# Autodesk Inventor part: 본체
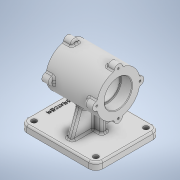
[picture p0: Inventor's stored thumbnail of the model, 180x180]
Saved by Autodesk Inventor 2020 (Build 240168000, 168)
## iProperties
Created: 2022-11
Part Number: 본체
Material: 일반
Document SubType Name: Modeling
Designer: owner
Density: 1 g/cm^3
Appearance: 기본값
Mass: 450.167 g
Surface Area: 796.807 cm^2
Volume: 450.167 cm^3
Author: owner
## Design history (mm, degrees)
sketch "스케치1"
  geometry: L1 (-65, -55)-(65, -55); L2 (65, -55)-(65, 55); L3 (65, 55)-(-65, 55); L4 (-65, 55)-(-65, -55); L5 (-65, -55)-(65, 55); L6 (65, -55)-(-65, 55); 1 further point
  constraints: 12 end point, 2 midpoint, 2 parallel, 1 horizontal, 1 perpendicular
  dimensions: "d0" = 130 distance of L3.end L2.end; "d1" = 110 distance of L2.end L1.end
extrude "돌출1" new body sketch "스케치1" distance "d2" = 12; taper "d3" = 0 deg
node "작업 평면1"
sketch "스케치3"
  geometry: L1 (110, 0)-(0, 0) reference; C1 r 37 at (55, 82); 2 further points
  constraints: 1 centre point, 1 midpoint, 1 vertical alignment
  dimensions: "d13" = 82 distance from line of L1 C1.centre; "d14" = 74 diameter of C1
extrude "돌출2" join sketch "스케치3" stored distance "d15" = 87; taper "d16" = 0 deg
sketch "스케치4"
  geometry: C1 r 37 at (0, 0) reference; A1 r 37 centre (0, 0) between (0, 37) and (-6.969, 36.338) reference; A2 r 7 centre (0, 37) between (6.969, 36.338) and (-6.969, 36.338); A3 r 7 centre (-37, 0) between (-36.338, 6.969) and (-36.338, -6.969); A4 r 7 centre (0, -37) between (-6.969, -36.338) and (6.969, -36.338); A5 r 7 centre (37, 0) between (36.338, -6.969) and (36.338, 6.969); 9 further points
  constraints: 11 point on circle, 4 centre point, 1 coincident, 1 vertical alignment, 17 other
  dimensions: "d17" = 14 diameter of A2; "d20" = 360 deg dimension on C1.centre A2.centre (derived)
extrude "돌출3" join sketch "스케치4" distance "d22" = 14; taper "d23" = 0 deg
sketch "스케치5"
  geometry: L1 (110, 0)-(0, 0) reference; L2 (0, 0)-(0, 12) reference; L3 (110, 12)-(0, 12) reference; L4 (110, 0)-(110, 12) reference; L5 (80.336, 55.036)-(96, 12); L6 (0, 12)-(110, 12) reference; L7 (29.664, 55.036)-(14, 12); A1 r 37 centre (55, 82) between (61.969, 45.662) and (91.338, 75.031) reference; A2 r 7 centre (55, 45) between (48.031, 45.662) and (61.969, 45.662) reference; A3 r 37 centre (55, 82) between (18.662, 75.031) and (48.031, 45.662) reference; A4 r 7 centre (18, 82) between (18.662, 88.969) and (18.662, 75.031) reference; A5 r 37 centre (55, 82) between (48.031, 118.338) and (18.662, 88.969) reference; A6 r 7 centre (55, 119) between (61.969, 118.338) and (48.031, 118.338) reference; A7 r 37 centre (55, 82) between (91.338, 88.969) and (61.969, 118.338) reference; A8 r 7 centre (92, 82) between (91.338, 75.031) and (91.338, 88.969) reference; A9 r 37 centre (55, 82) between (61.969, 45.662) and (91.338, 75.031) reference; A10 r 37 centre (55, 82) between (18.662, 75.031) and (48.031, 45.662) reference; A11 r 7 centre (55, 45) between (48.031, 45.662) and (61.969, 45.662) reference; A12 r 37 centre (55, 82) between (48.031, 45.662) and (61.969, 45.662) reference; 4 further points
  constraints: 4 end point, 2 point on circle, 2 point on line, 1 equal length
  dimensions: "d24" = 110 deg angle of L3 L5; "d25" = 110 deg angle of L3 L7; "d26" = 14 distance of L7.end L2.end
extrude "돌출4" join sketch "스케치5" stored distance "d27" = 10; taper "d28" = 0 deg
sketch "스케치6"
  geometry: L1 (-65, 0)-(65, 0) reference; L2 (65, 0)-(65, 12) reference; L3 (-65, 12)-(65, 12) reference; L4 (-65, 0)-(-65, 12) reference; L5 (0, 12)-(0, 55.036) reference; L6 (10, 55.036)-(10, 55.036) reference; L7 (10, 55.036)-(0, 55.036) reference; L8 (0, 55.036)-(0, 55.036) reference; L9 (0, 55.036)-(10, 55.036) reference; L10 (48.5, 45.662)-(34.5, 45.662) reference; L11 (34.5, 45.662)-(34.5, 45.662) reference; L12 (34.5, 45.662)-(48.5, 45.662) reference; L13 (48.5, 75.031)-(48.5, 45.662) reference; L14 (48.5, 75.031)-(34.5, 75.031) reference; L15 (34.5, 75.031)-(34.5, 88.969) reference; L16 (34.5, 88.969)-(48.5, 88.969) reference; L17 (48.5, 118.338)-(48.5, 88.969) reference; L18 (48.5, 118.338)-(34.5, 118.338) reference; L19 (34.5, 118.338)-(34.5, 118.338) reference; L20 (34.5, 118.338)-(48.5, 118.338) reference; L21 (48.5, 88.969)-(48.5, 118.338) reference; L22 (48.5, 88.969)-(34.5, 88.969) reference; L23 (34.5, 88.969)-(34.5, 75.031) reference; L24 (34.5, 75.031)-(48.5, 75.031) reference; L25 (48.5, 45.662)-(48.5, 75.031) reference; L26 (-38.5, 45.662)-(-24.5, 45.662) reference; L27 (-24.5, 45.662)-(-24.5, 45.662) reference; L28 (-24.5, 45.662)-(-38.5, 45.662) reference; L29 (-38.5, 75.031)-(-38.5, 45.662) reference; L30 (-38.5, 75.031)-(-24.5, 75.031) reference; L31 (-24.5, 75.031)-(-24.5, 88.969) reference; L32 (-24.5, 88.969)-(-38.5, 88.969) reference; L33 (-38.5, 118.338)-(-38.5, 88.969) reference; L34 (-38.5, 118.338)-(-24.5, 118.338) reference; L35 (-24.5, 118.338)-(-24.5, 118.338) reference; L36 (-24.5, 118.338)-(-38.5, 118.338) reference; L37 (-38.5, 88.969)-(-38.5, 118.338) reference; L38 (-38.5, 88.969)-(-24.5, 88.969) reference; L39 (-24.5, 88.969)-(-24.5, 75.031) reference; L40 (-24.5, 75.031)-(-38.5, 75.031) reference; L41 (-38.5, 45.662)-(-38.5, 75.031) reference; L42 (34.5, 45)-(-24.5, 45) reference; L43 (65, 12)-(-65, 12) reference; L44 (-15, 45)-(-15, 12); L45 (5, -25.2)-(5, 151.2) reference; 1 further point
  constraints: 2 end point, 2 point on line, 1 perpendicular
  dimensions: "d31" = 20 distance from line of L45 L44.end
feature "리브1" sketch "스케치6" dims "d32" = 1, "d33" = 10, "d34" = 0, "d35" = 0, "d36" = 1, "d37" = 1
sketch "스케치7"
  geometry: A1 r 7 centre (55, 45) between (48.031, 45.662) and (61.969, 45.662) reference; A2 r 37 centre (55, 82) between (61.969, 45.662) and (91.338, 75.031) reference; A3 r 7 centre (92, 82) between (91.338, 75.031) and (91.338, 88.969) reference; A4 r 37 centre (55, 82) between (91.338, 88.969) and (61.969, 118.338) reference; A5 r 7 centre (55, 119) between (61.969, 118.338) and (48.031, 118.338) reference; A6 r 37 centre (55, 82) between (48.031, 118.338) and (18.662, 88.969) reference; A7 r 7 centre (18, 82) between (18.662, 88.969) and (18.662, 75.031) reference; A8 r 37 centre (55, 82) between (18.662, 75.031) and (48.031, 45.662) reference; 1 further point
hole "구멍1" sketch "스케치7" at (55, 82) diameter "d38" = 42; stored, may be unused: countersink angle "d42" = 90 deg, drill point angle "d44" = 0 deg; dims "d39" = 8, "d40" = 47, "d41" = 19, "d43" = 87
sketch "스케치8"
  geometry: C1 r 21 at (-55, 82) reference; C2 r 23.5 at (-55, 82); 1 further point
  constraints: 1 centre point, 1 coincident
  dimensions: "d45" = 47 diameter of C2
extrude "돌출5" cut sketch "스케치8" distance "d46" = 19; taper "d47" = 0 deg
fillet "모깎기1" dims "d48" = 12
sketch "스케치10"
  geometry: A1 r 12 centre (-53, -43) between (-65, -43) and (-53, -55) reference; 2 further points
  constraints: 1 coincident
hole "구멍2" sketch "스케치10" at (-53, -43) diameter "d49" = 9; stored, may be unused: countersink angle "d53" = 90 deg, drill point angle "d55" = 0 deg; dims "d50" = 8, "d51" = 47, "d52" = 19, "d54" = 20
sketch "스케치12"
  geometry: L1 (55, 82)-(55, 132.865); C1 r 23.5 at (55, 82) reference; A1 r 37 centre (55, 82) between (61.969, 118.338) and (48.031, 118.338); A2 r 37 centre (55, 82) between (61.969, 118.338) and (48.031, 118.338) reference; 2 further points
  constraints: 2 end point, 1 centre point, 1 coincident, 1 point on circle, 1 point on line, 1 vertical
  dimensions: "d56" = 74 diameter of A1
hole "구멍3" sketch "스케치12" at (55, 119) diameter "d57" = 3.242; stored, may be unused: countersink angle "d61" = 90 deg, drill point angle "d63" = 0 deg; dims "d58" = 8, "d59" = 47, "d60" = 19, "d62" = 10
fillet "모깎기2" dims "d67" = 3
fillet "모깎기3" dims "d68" = 3
fillet "모깎기4" dims "d69" = 3
fillet "모깎기5" dims "d70" = 3
fillet "모깎기6" dims "d71" = 3
fillet "모깎기7" dims "d72" = 3
fillet "모깎기8" dims "d73" = 3
chamfer "모따기1" distance "d74" = 1; stored, may be unused: second distance "d75" = 2, angle "d76" = 45 deg
fillet "모깎기9" dims "d77" = 1
sketch "스케치13"
  geometry: 1 further point
sketch "스케치14"
  geometry: L1 (5, -77)-(5, 77) reference; L2 (-65, 43)-(-65, -43) reference; 3 further points
  constraints: 1 horizontal alignment, 1 midpoint, 1 other
  dimensions: "d78" = 58 distance from line of point (-53, 0) L1
feature "엠보싱1" sketch "스케치14" dims "d0" = 130, "d1" = 110, "d79" = 0.5, "d80" = 0
node "솔리드1"
mirror "미러1"
mirror "미러2"
mirror "미러3"
mirror "미러4"
pattern_circular "원형 패턴1" dims angle "d65" = 360 deg
mirror "미러5"
node "투영된 루프1"
node "투영된 루프2"
node "투영된 루프3"
node "투영된 루프4"
node "투영된 루프5"
node "작업 평면2"
node "투영된 루프6"
feature "A9D066F2-1C7D-4E18-AEED-F7BC21143FA4" dims "d38" = 42, "d39" = 8, "d40" = 47, "d41" = 19, "d42" = 90 deg, "d43" = 87, "d44" = 0
